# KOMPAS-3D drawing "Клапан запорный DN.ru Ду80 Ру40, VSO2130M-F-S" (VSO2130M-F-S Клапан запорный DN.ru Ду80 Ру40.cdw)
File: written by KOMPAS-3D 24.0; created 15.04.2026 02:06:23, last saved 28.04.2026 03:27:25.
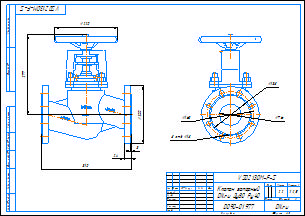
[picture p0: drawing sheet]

Document properties: Автор: DN.ru; Форматы листов документа: A3; Полное имя файла: VSO2130M-F-S Клапан запорный DN.ru Ду80 Ру40.m3d; Масса: 22; Наименование: Клапан запорный DN.ru Ду80 Ру40; Количество листов документа: 1; Примечание: D090-01977

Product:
- Part/product: Клапан запорный DN.ru Ду80 Ру40  | designation VSO2130M-F-S
    Масса: 22
    Раздел спецификации: Прочие изделия
    Примечание: D090-01977

Views: Вид 1, Вид:1, Проекционный вид 2
Referenced files in C:\Работа\VSO2130M-F-S Клапан запорный DN.ru\DN20\: VSO2130M-F-S DN20 PN40  Клапан запорный сильфонный DN.ru.m3d
Referenced files in C:\Работа\VSO2130M-F-S Клапан запорный DN.ru\DN80\: VSO2130M-F-S Клапан запорный DN.ru Ду80 Ру40.m3d
Referenced files in C:\Program Files\ASCON\KOMPAS-3D v24\Templates\: Чертеж_DN.ru.cdt
Referenced files in C:\Работа\ГОТОВЫЕ ИСХОДНИКИ\VSO2130M-F-S Клапан запорный сильфонный DN.ru Ду15-100 Ру40\DN80\: VSO2130M-F-S Клапан запорный DN.ru Ду80 Ру40.m3d
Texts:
  VSO2130M-F-S
  Чертеж_DN.ru.cdt
  Клапан запорный
  DN.ru Ду80 Ру40
  Клапан запорный DN.ru Ду80 Ру40
  VSO2130M-F-S  Клапан запорный DN.ru Ду80 Ру40
Dimensions and other numbers on the sheet: 0; 3; 2; 4; 200; 310; 24; 277; 220; 1; 5; 76; 138; 160; 8 отв.; 18; 1:2,5; 22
